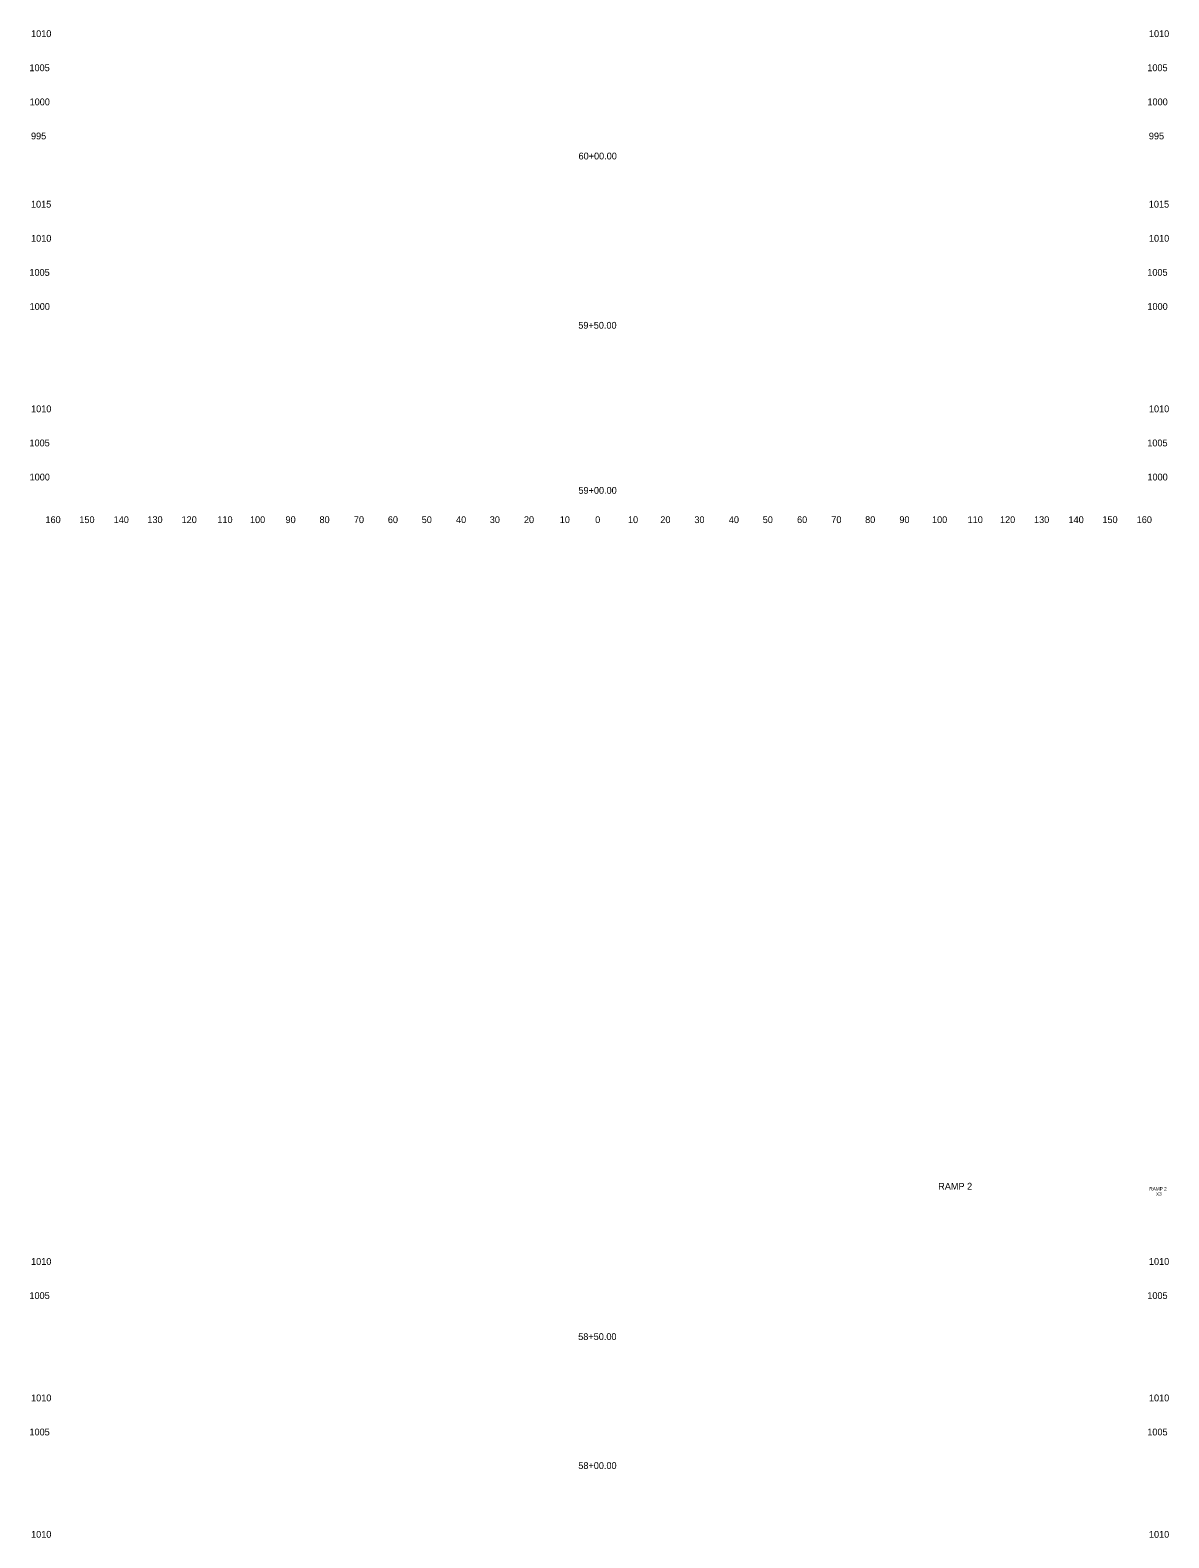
# Model space of a CAD drawing. Extents: x 4994 to 5328, y 4997 to 8804.
# Drawn here: x 4993.6 to 5327.5, y 5900 to 6342 of the extents above; entities that cross this region are included whole.
import ezdxf

# ---------------------------------------------------------------- set-up
doc = ezdxf.new("R2010")
doc.units = 0
for name, color, linetype in [('RD_SHT_ID', 7, 'Continuous'), ('RD_XS_TX_Offset', 7, 'Continuous'), ('RD_XS_TX_Station', 7, 'Continuous')]:
    doc.layers.add(name, color=color, linetype=linetype)

msp = doc.modelspace()

# ---------------------------------------------------------------- texts
at = {"layer": 'RD_SHT_ID'}
for s, height, p in [('RAMP 2', 2, (5259.89, 6002.06)), ('RAMP 2', 1, (5321.78, 6001.8)), ('X3', 1, (5323.74, 6000.3))]:
    msp.add_text(s, height=height, dxfattribs=at).set_placement(p)
at = {"layer": 'RD_XS_TX_Offset'}
for s, p in [('1010', (4993.88, 6340)), ('1010', (5321.68, 6340)), ('1005', (4993.4, 6330)), ('1005', (5321.2, 6330)), ('1000', (4993.44, 6320)), ('1000', (5321.24, 6320)), ('995', (4993.86, 6310)), ('995', (5321.66, 6310)), ('1015', (4993.85, 6290)), ('1015', (5321.65, 6290)), ('1010', (4993.88, 6280)), ('1010', (5321.68, 6280)), ('1005', (4993.4, 6270)), ('1005', (5321.2, 6270)), ('1000', (4993.44, 6260)), ('1000', (5321.24, 6260)), ('1010', (4993.88, 6230)), ('1010', (5321.68, 6230)), ('1005', (4993.4, 6220)), ('1005', (5321.2, 6220)), ('1000', (4993.44, 6210)), ('1000', (5321.24, 6210)), ('160', (4998.1, 6197.5)), ('150', (5008.04, 6197.5)), ('140', (5018.1, 6197.5)), ('130', (5027.99, 6197.5)), ('120', (5038.01, 6197.5)), ('110', (5048.51, 6197.5)), ('100', (5058.07, 6197.5)), ('90', (5068.5, 6197.5)), ('80', (5078.46, 6197.5)), ('70', (5088.54, 6197.5)), ('60', (5098.5, 6197.5)), ('50', (5108.43, 6197.5)), ('40', (5118.5, 6197.5)), ('30', (5128.39, 6197.5)), ('20', (5138.4, 6197.5)), ('10', (5148.91, 6197.5)), ('0', (5159.3, 6197.5)), ('0', (5159.3, 6197.5)), ('10', (5168.91, 6197.5)), ('20', (5178.4, 6197.5)), ('30', (5188.39, 6197.5)), ('40', (5198.5, 6197.5)), ('50', (5208.43, 6197.5)), ('60', (5218.5, 6197.5)), ('70', (5228.54, 6197.5)), ('80', (5238.46, 6197.5)), ('90', (5248.5, 6197.5)), ('100', (5258.07, 6197.5)), ('110', (5268.51, 6197.5)), ('120', (5278.01, 6197.5)), ('130', (5287.99, 6197.5)), ('140', (5298.1, 6197.5)), ('150', (5308.04, 6197.5)), ('160', (5318.1, 6197.5)), ('1010', (4993.88, 5980)), ('1010', (5321.68, 5980)), ('1005', (4993.4, 5970)), ('1005', (5321.2, 5970)), ('1010', (4993.88, 5940)), ('1010', (5321.68, 5940)), ('1005', (4993.4, 5930)), ('1005', (5321.2, 5930)), ('1010', (4993.88, 5900)), ('1010', (5321.68, 5900))]:
    msp.add_text(s, height=2, dxfattribs=at).set_placement(p)
at = {"layer": 'RD_XS_TX_Station'}
for s, p in [('60+00.00', (5154.42, 6304.12)), ('59+50.00', (5154.35, 6254.49)), ('59+00.00', (5154.39, 6206.09)), ('58+50.00', (5154.32, 5957.97)), ('58+00.00', (5154.35, 5920.16))]:
    msp.add_text(s, height=2, dxfattribs=at).set_placement(p)

doc.saveas('drawing.dxf')
